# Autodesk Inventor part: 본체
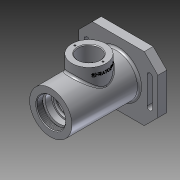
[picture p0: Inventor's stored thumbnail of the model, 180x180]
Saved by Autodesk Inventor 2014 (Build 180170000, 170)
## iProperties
Created: 2017-10
Part Number: 본체
Material: 알루미늄 6061
Document SubType Name: Modeling
Designer: net
Density: 2.71 g/cm^3
Appearance: 알루미늄 - 평지
Mass: 789.296 g
Surface Area: 668.608 cm^2
Volume: 291.253 cm^3
Author: net
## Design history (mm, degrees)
sketch "스케치1"
  geometry: L1 (-58, 47)-(58, 47); L2 (58, 47)-(58, -47); L3 (58, -47)-(-58, -47); L4 (-58, -47)-(-58, 47); L5 (-46, 20)-(-46, -20); L6 (-50, 20)-(-50, -20); L7 (-42, -20)-(-42, 20); L8 (46, 20)-(46, -20); L9 (42, 20)-(42, -20); L10 (50, -20)-(50, 20); A1 r 4 centre (-46, 20) between (-42, 20) and (-50, 20); A2 r 4 centre (-46, -20) between (-50, -20) and (-42, -20); A3 r 4 centre (46, 20) between (50, 20) and (42, 20); A4 r 4 centre (46, -20) between (42, -20) and (50, -20); 5 further points
  constraints: 24 end point, 8 point on circle, 8 tangent, 6 parallel, 4 centre point, 4 midpoint, 3 horizontal alignment, 1 horizontal, 1 perpendicular, 1 vertical alignment
  dimensions: "d0" = 94 distance of L1.end L2.end; "d1" = 116 distance of L1.start L1.end; "d2" = 4 radius of A3; "d3" = 4 radius of A1; "d4" = 40 distance of L8.end L8.start; "d5" = 40 distance of L5.end L5.start; "d6" = 46 distance of point (0, 0) point (-46, 0); "d7" = 92 distance of point (46, 0) point (-46, 0)
extrude "돌출1" new body sketch "스케치1" distance "d8" = 13; taper "d9" = 0 deg
sketch "스케치2"
  geometry: C1 r 31 at (0, 0); 1 further point
  constraints: 1 centre point, 1 coincident
  dimensions: "d10" = 62 diameter of C1
extrude "돌출2" join sketch "스케치2" distance "d11" = 99; taper "d12" = 0 deg
sketch "스케치3"
  geometry: C1 r 35 at (0, 0); 1 further point
  constraints: 1 centre point, 1 coincident
  dimensions: "d13" = 70 diameter of C1
extrude "돌출3" join sketch "스케치3" distance "d14" = 3; taper "d15" = 0 deg
sketch "스케치4"
  geometry: L1 (-35, -3)-(35, -3) reference; L2 (31, 112)-(-31, 112) reference; L3 (0, 112)-(0, -3); L4 (21, 112)-(21, 103); L5 (21, 103)-(24, 103); L6 (24, 103)-(24, 100); L7 (24, 100)-(20, 100); L8 (20, 100)-(20, 91); L9 (20, 91)-(17.5, 91); L10 (17.5, 91)-(17.5, 87.75); L11 (17.5, 87.75)-(18.5, 87.75); L12 (18.5, 87.75)-(18.5, 86); L13 (18.5, 86)-(17.5, 86); L14 (17.5, 86)-(17.5, 75); L15 (17.5, 75)-(26, 75); L16 (26, 75)-(26, 37); L17 (26, 37)-(17.5, 37); L18 (17.5, 37)-(17.5, 26); L19 (17.5, 26)-(16.5, 26); L20 (16.5, 26)-(16.5, 21); L21 (16.5, 21)-(10, 21); L22 (10, 21)-(10, 18.3); L23 (10, 18.3)-(12.5, 18.3); L24 (12.5, 18.3)-(12.5, 11); L25 (12.5, 11)-(16, 11); L26 (16, 11)-(22, -3); 1 further point
  constraints: 48 end point, 17 parallel, 4 perpendicular, 2 collinear, 2 midpoint, 2 point on line, 1 horizontal
  dimensions: "d69" = 42 diameter of L4 L3; "d70" = 48 diameter of L6 L3; "d71" = 40 diameter of L8 L3; "d72" = 35 diameter of L10 L3; "d73" = 37 diameter of L12 L3; "d74" = 52 diameter of L16 L3; "d75" = 33 diameter of L20 L3; "d76" = 20 diameter of L22 L3; "d77" = 25 diameter of L24 L3; "d78" = 32 diameter of L25.end L3; "d79" = 44 diameter of L26.end L3; "d80" = 12 distance between parallel lines of L7 L2; "d81" = 3 distance of L5.end L6.end; "d82" = 21 distance between parallel lines of L2 L9; "d83" = 26 distance from line of L2 L13.end; "d84" = 1.75 distance of L11.end L12.end; "d85" = 11 distance from line of L15 L12.end; "d86" = 38 distance between parallel lines of L17 L15; "d87" = 11 distance from line of L19.end L17; "d88" = 14 distance between parallel lines of L1 L25; "d100" = 5 distance from line of L21 L18.end; "d102" = 2.7 distance from line of L22.end L21
node "작업 평면1"
sketch "스케치5"
  geometry: L1 (31, 112)-(-31, 112) reference; L2 (58, 0)-(-58, 0) reference; C1 r 25 at (0, 56); 2 further points
  constraints: 1 centre point, 1 midpoint, 1 vertical alignment
  dimensions: "d39" = 50 diameter of C1; "d40" = 56 distance from line of C1.centre L1
extrude "돌출4" join sketch "스케치5" distance "d41" = 50 (= d39); taper "d42" = 0 deg
sketch "스케치6"
  geometry: C1 r 25 at (0, 0) reference; C2 r 16 at (0, 0); 1 further point
  constraints: 1 centre point, 1 coincident
  dimensions: "d43" = 32 diameter of C2
extrude "돌출5" cut sketch "스케치6" distance "d44" = 50 (= d39); taper "d45" = 0 deg
sketch "스케치7"
  geometry: C1 r 16 at (0, 0) reference; C2 r 25 at (0, 0) reference; 1 further point
sketch "스케치8"
  geometry: L1 (0, 94)-(0, 0) reference; L2 (0, 94)-(-13, 94) reference; L3 (-13, 0)-(-13, 94) reference; L4 (0, 0)-(-13, 0) reference; 1 further point
sketch "스케치9"
  geometry: C1 r 16 at (0, 0) reference; 2 further points
  constraints: 1 horizontal alignment
  dimensions: "d46" = 20.5 distance of point (20.5, 0) C1.centre
hole "구멍1" sketch "스케치9" at (20.5, 0) diameter "d47" = 2.459; stored, may be unused: countersink angle "d51" = 90 deg, drill point angle "d53" = 118 deg; dims "d48" = 6, "d49" = 4, "d50" = 2, "d52" = 8
chamfer "모따기1" distance "d57" = 20; stored, may be unused: second distance "d58" = 2, angle "d59" = 45 deg
node "작업 평면2"
sketch "스케치10"
  geometry: L1 (0, 25)-(0, -25) reference; L2 (-16, 56)-(-78, 56) reference; 2 further points
  constraints: 1 other
  dimensions: "d60" = 10 distance from line of point (-10, 0) L1; "d61" = 56 distance from line of point (-10, 0) L2
feature "엠보싱1" sketch "스케치10" dims "d0" = 94, "d1" = 116, "d2" = 4, "d3" = 4, "d4" = 40, "d5" = 40, "d6" = 46, "d7" = 92, "d10" = 62, "d62" = 0.5, "d63" = 0
revolve "회전1" stored, may be unused: angle "d91" = 90 deg
feature "스레드1" dims "d92" = 10, "d93" = 0
chamfer "모따기2" distance "d94" = 1; stored, may be unused: second distance "d95" = 2, angle "d96" = 45 deg
fillet "모깎기1" dims "d97" = 3
fillet "모깎기2" dims "d98" = 3
fillet "모깎기3" dims "d99" = 0.3
node "솔리드1"
pattern_circular "원형 패턴1" dims angle "d55" = 360 deg
other parameters: "d38" = 47
